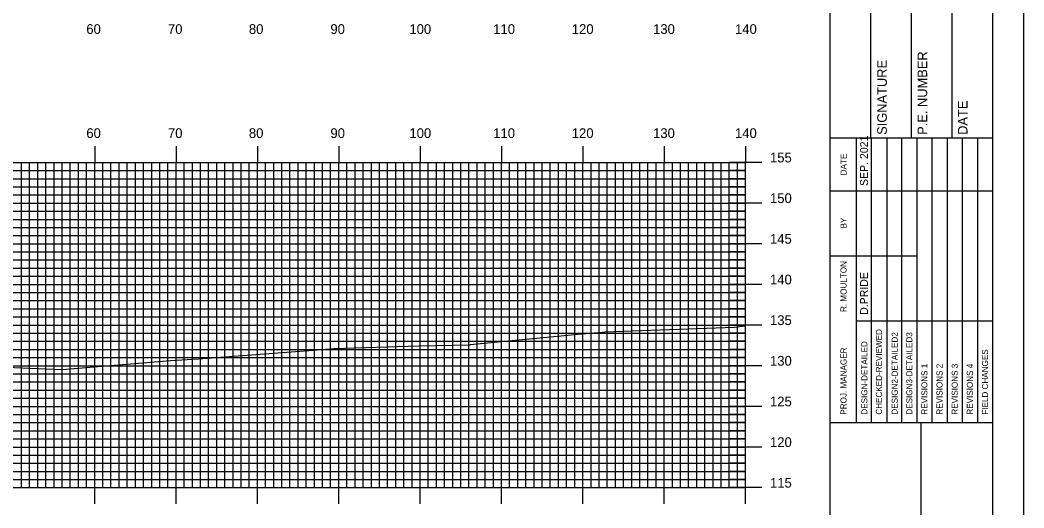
# Model space of a CAD drawing. Extents: x 851360 to 851703, y 364661 to 364881.
# Drawn here: x 851576.6 to 851699.9, y 364746.9 to 364806.9 of the extents above; entities that cross this region are included whole.
import ezdxf

# ---------------------------------------------------------------- set-up
doc = ezdxf.new("R2010")
doc.units = 0
for name, color, linetype in [('BORDER', 7, 'Continuous'), ('H_V ANNOTATION', 7, 'Continuous'), ('MAJOR', 7, 'Continuous'), ('MINOR', 7, 'Continuous'), ('PLOT BOUNDARY', 7, 'Continuous'), ('S_Roadway_Centerline', 7, 'Continuous')]:
    doc.layers.add(name, color=color, linetype=linetype)

msp = doc.modelspace()

# ---------------------------------------------------------------- linework, layer by layer
at = {"layer": 'BORDER'}
for p, q in [((851676.13, 364667.37), (851676.13, 364877.37)), ((851681.13, 364792.38), (851681.13, 364809.67)), ((851686.13, 364792.38), (851686.13, 364809.67)), ((851691.13, 364792.38), (851691.13, 364809.67)), ((851676.13, 364792.38), (851696.13, 364792.38)), ((851676.13, 364757.38), (851696.13, 364757.38)), ((851687.31, 364687.38), (851687.31, 364757.38))]:
    msp.add_line(p, q, dxfattribs=at)
msp.add_lwpolyline([(851376.13, 364667.37), (851696.13, 364667.37), (851696.13, 364877.37), (851376.13, 364877.37)], close=True, dxfattribs=at)
for points in [[(851679.36, 364785.88), (851679.36, 364792.38)], [(851681.22, 364757.38), (851681.22, 364792.38)], [(851683.09, 364792.38), (851683.09, 364757.38)], [(851684.95, 364757.38), (851684.95, 364792.38)], [(851686.81, 364757.38), (851686.81, 364792.38)], [(851688.68, 364757.38), (851688.68, 364792.38)], [(851690.54, 364757.38), (851690.54, 364792.38)], [(851692.4, 364757.38), (851692.4, 364792.38)], [(851694.27, 364757.38), (851694.27, 364792.38)], [(851679.36, 364757.38), (851679.36, 364790.96)], [(851676.13, 364785.88), (851696.13, 364785.88)], [(851676.13, 364777.88), (851679.36, 364777.88)], [(851679.36, 364777.88), (851686.81, 364777.88)], [(851679.36, 364769.88), (851696.13, 364769.88)]]:
    msp.add_lwpolyline(points, dxfattribs=at)
at = {"layer": 'MAJOR'}
for p, q in [((851585.73, 364791.37), (851585.73, 364789.37)), ((851595.73, 364791.37), (851595.73, 364789.37)), ((851605.73, 364791.37), (851605.73, 364789.37)), ((851615.73, 364791.37), (851615.73, 364789.37)), ((851625.73, 364791.37), (851625.73, 364789.37)), ((851635.73, 364791.37), (851635.73, 364789.37)), ((851645.73, 364791.37), (851645.73, 364789.37)), ((851655.73, 364791.37), (851655.73, 364789.37)), ((851665.73, 364791.37), (851665.73, 364789.37)), ((851385.73, 364789.37), (851665.73, 364789.37)), ((851385.73, 364789.37), (851665.73, 364789.37)), ((851585.73, 364749.37), (851585.73, 364789.37)), ((851595.73, 364749.37), (851595.73, 364789.37)), ((851605.73, 364749.37), (851605.73, 364789.37)), ((851615.73, 364749.37), (851615.73, 364789.37)), ((851625.73, 364749.37), (851625.73, 364789.37)), ((851635.73, 364749.37), (851635.73, 364789.37)), ((851645.73, 364749.37), (851645.73, 364789.37)), ((851655.73, 364749.37), (851655.73, 364789.37)), ((851667.73, 364789.37), (851663.72, 364789.37)), ((851665.73, 364749.37), (851665.73, 364789.37)), ((851665.73, 364749.37), (851665.73, 364789.37)), ((851385.73, 364784.37), (851665.73, 364784.37)), ((851667.73, 364784.37), (851663.72, 364784.37)), ((851385.73, 364779.37), (851665.73, 364779.37)), ((851667.73, 364779.37), (851663.72, 364779.37)), ((851385.73, 364774.37), (851665.73, 364774.37)), ((851667.73, 364774.37), (851663.72, 364774.37)), ((851385.73, 364769.37), (851665.73, 364769.37)), ((851667.73, 364769.37), (851663.72, 364769.37)), ((851385.73, 364764.37), (851665.73, 364764.37)), ((851667.73, 364764.37), (851663.72, 364764.37)), ((851385.73, 364759.37), (851665.73, 364759.37)), ((851667.73, 364759.37), (851663.72, 364759.37)), ((851385.73, 364754.37), (851665.73, 364754.37)), ((851667.73, 364754.37), (851663.72, 364754.37)), ((851385.73, 364749.37), (851665.73, 364749.37)), ((851385.73, 364749.37), (851665.73, 364749.37)), ((851585.73, 364747.37), (851585.73, 364749.37)), ((851595.73, 364747.37), (851595.73, 364749.37)), ((851605.73, 364747.37), (851605.73, 364749.37)), ((851615.73, 364747.37), (851615.73, 364749.37)), ((851625.73, 364747.37), (851625.73, 364749.37)), ((851635.73, 364747.37), (851635.73, 364749.37)), ((851645.73, 364747.37), (851645.73, 364749.37)), ((851655.73, 364747.37), (851655.73, 364749.37)), ((851667.73, 364749.37), (851663.72, 364749.37)), ((851665.73, 364747.37), (851665.73, 364749.37))]:
    msp.add_line(p, q, dxfattribs=at)
at = {"layer": 'MINOR'}
for p, q in [((851576.73, 364749.37), (851576.73, 364789.37)), ((851577.73, 364749.37), (851577.73, 364789.37)), ((851578.73, 364749.37), (851578.73, 364789.37)), ((851579.73, 364749.37), (851579.73, 364789.37)), ((851580.73, 364749.37), (851580.73, 364789.37)), ((851581.73, 364749.37), (851581.73, 364789.37)), ((851582.73, 364749.37), (851582.73, 364789.37)), ((851583.73, 364749.37), (851583.73, 364789.37)), ((851584.73, 364749.37), (851584.73, 364789.37)), ((851586.73, 364749.37), (851586.73, 364789.37)), ((851587.73, 364749.37), (851587.73, 364789.37)), ((851588.73, 364749.37), (851588.73, 364789.37)), ((851589.73, 364749.37), (851589.73, 364789.37)), ((851590.73, 364749.37), (851590.73, 364789.37)), ((851591.73, 364749.37), (851591.73, 364789.37)), ((851592.73, 364749.37), (851592.73, 364789.37)), ((851593.73, 364749.37), (851593.73, 364789.37)), ((851594.73, 364749.37), (851594.73, 364789.37)), ((851596.73, 364749.37), (851596.73, 364789.37)), ((851597.73, 364749.37), (851597.73, 364789.37)), ((851598.73, 364749.37), (851598.73, 364789.37)), ((851599.73, 364749.37), (851599.73, 364789.37)), ((851600.73, 364749.37), (851600.73, 364789.37)), ((851601.73, 364749.37), (851601.73, 364789.37)), ((851602.73, 364749.37), (851602.73, 364789.37)), ((851603.73, 364749.37), (851603.73, 364789.37)), ((851604.73, 364749.37), (851604.73, 364789.37)), ((851606.73, 364749.37), (851606.73, 364789.37)), ((851607.73, 364749.37), (851607.73, 364789.37)), ((851608.73, 364749.37), (851608.73, 364789.37)), ((851609.73, 364749.37), (851609.73, 364789.37)), ((851610.73, 364749.37), (851610.73, 364789.37)), ((851611.73, 364749.37), (851611.73, 364789.37)), ((851612.73, 364749.37), (851612.73, 364789.37)), ((851613.73, 364749.37), (851613.73, 364789.37)), ((851614.73, 364749.37), (851614.73, 364789.37)), ((851616.73, 364749.37), (851616.73, 364789.37)), ((851617.73, 364749.37), (851617.73, 364789.37)), ((851618.73, 364749.37), (851618.73, 364789.37)), ((851619.73, 364749.37), (851619.73, 364789.37)), ((851620.73, 364749.37), (851620.73, 364789.37)), ((851621.73, 364749.37), (851621.73, 364789.37)), ((851622.73, 364749.37), (851622.73, 364789.37)), ((851623.73, 364749.37), (851623.73, 364789.37)), ((851624.73, 364749.37), (851624.73, 364789.37)), ((851626.73, 364749.37), (851626.73, 364789.37)), ((851627.73, 364749.37), (851627.73, 364789.37)), ((851628.73, 364749.37), (851628.73, 364789.37)), ((851629.73, 364749.37), (851629.73, 364789.37)), ((851630.73, 364749.37), (851630.73, 364789.37)), ((851631.73, 364749.37), (851631.73, 364789.37)), ((851632.73, 364749.37), (851632.73, 364789.37)), ((851633.73, 364749.37), (851633.73, 364789.37)), ((851634.73, 364749.37), (851634.73, 364789.37)), ((851636.73, 364749.37), (851636.73, 364789.37)), ((851637.73, 364749.37), (851637.73, 364789.37)), ((851638.73, 364749.37), (851638.73, 364789.37)), ((851639.73, 364749.37), (851639.73, 364789.37)), ((851640.73, 364749.37), (851640.73, 364789.37)), ((851641.73, 364749.37), (851641.73, 364789.37)), ((851642.73, 364749.37), (851642.73, 364789.37)), ((851643.73, 364749.37), (851643.73, 364789.37)), ((851644.73, 364749.37), (851644.73, 364789.37)), ((851646.73, 364749.37), (851646.73, 364789.37)), ((851647.73, 364749.37), (851647.73, 364789.37)), ((851648.73, 364749.37), (851648.73, 364789.37)), ((851649.73, 364749.37), (851649.73, 364789.37)), ((851650.73, 364749.37), (851650.73, 364789.37)), ((851651.73, 364749.37), (851651.73, 364789.37)), ((851652.73, 364749.37), (851652.73, 364789.37)), ((851653.73, 364749.37), (851653.73, 364789.37)), ((851654.73, 364749.37), (851654.73, 364789.37)), ((851656.73, 364749.37), (851656.73, 364789.37)), ((851657.73, 364749.37), (851657.73, 364789.37)), ((851658.73, 364749.37), (851658.73, 364789.37)), ((851659.73, 364749.37), (851659.73, 364789.37)), ((851660.73, 364749.37), (851660.73, 364789.37)), ((851661.73, 364749.37), (851661.73, 364789.37)), ((851662.73, 364749.37), (851662.73, 364789.37)), ((851663.73, 364749.37), (851663.73, 364789.37)), ((851664.73, 364749.37), (851664.73, 364789.37)), ((851385.73, 364788.37), (851665.73, 364788.37)), ((851665.73, 364788.37), (851663.72, 364788.37)), ((851385.73, 364787.37), (851665.73, 364787.37)), ((851665.73, 364787.37), (851663.72, 364787.37)), ((851385.73, 364786.37), (851665.73, 364786.37)), ((851665.73, 364786.37), (851663.72, 364786.37)), ((851385.73, 364785.37), (851665.73, 364785.37)), ((851665.73, 364785.37), (851663.72, 364785.37)), ((851385.73, 364783.37), (851665.73, 364783.37)), ((851665.73, 364783.37), (851663.72, 364783.37)), ((851385.73, 364782.37), (851665.73, 364782.37)), ((851665.73, 364782.37), (851663.72, 364782.37)), ((851385.73, 364781.37), (851665.73, 364781.37)), ((851665.73, 364781.37), (851663.72, 364781.37)), ((851385.73, 364780.37), (851665.73, 364780.37)), ((851665.73, 364780.37), (851663.72, 364780.37)), ((851385.73, 364778.37), (851665.73, 364778.37)), ((851665.73, 364778.37), (851663.72, 364778.37)), ((851385.73, 364777.37), (851665.73, 364777.37)), ((851665.73, 364777.37), (851663.72, 364777.37)), ((851385.73, 364776.37), (851665.73, 364776.37)), ((851665.73, 364776.37), (851663.72, 364776.37)), ((851385.73, 364775.37), (851665.73, 364775.37)), ((851665.73, 364775.37), (851663.72, 364775.37)), ((851385.73, 364773.37), (851665.73, 364773.37)), ((851665.73, 364773.37), (851663.72, 364773.37)), ((851385.73, 364772.37), (851665.73, 364772.37)), ((851665.73, 364772.37), (851663.72, 364772.37)), ((851385.73, 364771.37), (851665.73, 364771.37)), ((851665.73, 364771.37), (851663.72, 364771.37)), ((851385.73, 364770.37), (851665.73, 364770.37)), ((851665.73, 364770.37), (851663.72, 364770.37)), ((851385.73, 364768.37), (851665.73, 364768.37)), ((851665.73, 364768.37), (851663.72, 364768.37)), ((851385.73, 364767.37), (851665.73, 364767.37)), ((851665.73, 364767.37), (851663.72, 364767.37)), ((851385.73, 364766.37), (851665.73, 364766.37)), ((851665.73, 364766.37), (851663.72, 364766.37)), ((851385.73, 364765.37), (851665.73, 364765.37)), ((851665.73, 364765.37), (851663.72, 364765.37)), ((851385.73, 364763.37), (851665.73, 364763.37)), ((851665.73, 364763.37), (851663.72, 364763.37)), ((851385.73, 364762.37), (851665.73, 364762.37)), ((851665.73, 364762.37), (851663.72, 364762.37)), ((851385.73, 364761.37), (851665.73, 364761.37)), ((851665.73, 364761.37), (851663.72, 364761.37)), ((851385.73, 364760.37), (851665.73, 364760.37)), ((851665.73, 364760.37), (851663.72, 364760.37)), ((851385.73, 364758.37), (851665.73, 364758.37)), ((851665.73, 364758.37), (851663.72, 364758.37)), ((851385.73, 364757.37), (851665.73, 364757.37)), ((851665.73, 364757.37), (851663.72, 364757.37)), ((851385.73, 364756.37), (851665.73, 364756.37)), ((851665.73, 364756.37), (851663.72, 364756.37)), ((851385.73, 364755.37), (851665.73, 364755.37)), ((851665.73, 364755.37), (851663.72, 364755.37)), ((851385.73, 364753.37), (851665.73, 364753.37)), ((851665.73, 364753.37), (851663.72, 364753.37)), ((851385.73, 364752.37), (851665.73, 364752.37)), ((851665.73, 364752.37), (851663.72, 364752.37)), ((851385.73, 364751.37), (851665.73, 364751.37)), ((851665.73, 364751.37), (851663.72, 364751.37)), ((851385.73, 364750.37), (851665.73, 364750.37)), ((851665.73, 364750.37), (851663.72, 364750.37))]:
    msp.add_line(p, q, dxfattribs=at)
at = {"layer": 'PLOT BOUNDARY'}
msp.add_lwpolyline([(851359.94, 364661.25), (851699.94, 364661.25), (851699.94, 364881.25), (851359.94, 364881.25)], close=True, dxfattribs=at)
at = {"layer": 'S_Roadway_Centerline'}
msp.add_lwpolyline([(851559.47, 364768.31), (851561.23, 364767.57), (851567.4, 364764.87), (851570.49, 364764.42), (851570.98, 364764.29), (851571.91, 364764.3), (851581.71, 364763.92), (851595.03, 364765.01), (851598.49, 364765.23), (851612.59, 364766.27), (851615.1, 364766.47), (851625.58, 364766.82), (851631.89, 364766.92), (851631.89, 364766.98), (851645.16, 364768.24), (851648.11, 364768.51), (851648.41, 364768.53), (851654.09, 364768.73), (851664.38, 364769.1), (851664.99, 364769.18), (851665.73, 364769.27)], dxfattribs=at)

# ---------------------------------------------------------------- texts
at = {"layer": 'BORDER'}
for s, height, p in [('P.E. NUMBER', 1.1811, (851688.05, 364792.76)), ('SIGNATURE', 1.181, (851683.09, 364792.76)), ('DATE', 1.181, (851693.01, 364792.76)), ('SEP. 2021', 0.969, (851680.77, 364786.47)), ('DATE', 0.743, (851678.14, 364787.79)), ('BY', 0.743, (851678.14, 364781.25)), ('R. MOULTON', 0.745, (851678.14, 364770.98)), ('D.PRIDE', 0.969, (851680.77, 364770.62)), ('CHECKED-REVIEWED', 0.7455, (851682.49, 364758.35)), ('DESIGN2-DETAILED2', 0.7455, (851684.43, 364758.35)), ('DESIGN3-DETAILED3', 0.7455, (851686.22, 364758.35)), ('DESIGN-DETAILED', 0.7455, (851680.7, 364758.35)), ('PROJ. MANAGER', 0.7455, (851678.14, 364758.35)), ('FIELD CHANGES', 0.7455, (851695.53, 364758.35)), ('REVISIONS 1', 0.7455, (851688.08, 364758.35)), ('REVISIONS 2', 0.7455, (851689.94, 364758.35)), ('REVISIONS 3', 0.7455, (851691.81, 364758.35)), ('REVISIONS 4', 0.7455, (851693.67, 364758.35))]:
    msp.add_text(s, height=height, rotation=90, dxfattribs=at).set_placement(p)
at = {"layer": 'H_V ANNOTATION'}
for s, p in [('60', (851584.7, 364805.17)), ('70', (851594.73, 364805.17)), ('80', (851604.68, 364805.17)), ('90', (851614.7, 364805.17)), ('100', (851624.41, 364805.17)), ('110', (851634.71, 364805.17)), ('120', (851644.37, 364805.17)), ('130', (851654.36, 364805.17)), ('140', (851664.43, 364805.17)), ('60', (851584.7, 364792.37)), ('70', (851594.73, 364792.37)), ('80', (851604.68, 364792.37)), ('90', (851614.7, 364792.37)), ('100', (851624.41, 364792.37)), ('110', (851634.71, 364792.37)), ('120', (851644.37, 364792.37)), ('130', (851654.36, 364792.37)), ('140', (851664.43, 364792.37)), ('155', (851668.73, 364789.37)), ('150', (851668.73, 364784.37)), ('145', (851668.73, 364779.37)), ('140', (851668.73, 364774.37)), ('135', (851668.73, 364769.37)), ('130', (851668.73, 364764.37)), ('125', (851668.73, 364759.37)), ('120', (851668.73, 364754.37)), ('115', (851668.73, 364749.37))]:
    msp.add_text(s, height=1.2, dxfattribs=at).set_placement(p)

doc.saveas('drawing.dxf')
